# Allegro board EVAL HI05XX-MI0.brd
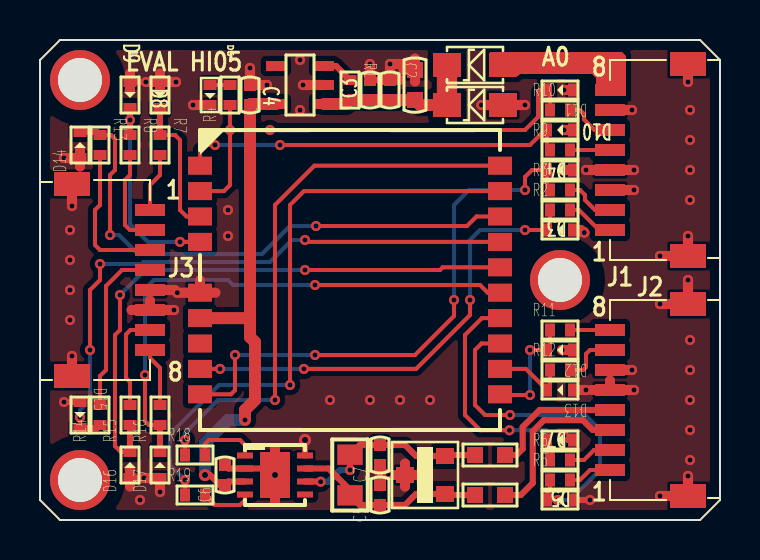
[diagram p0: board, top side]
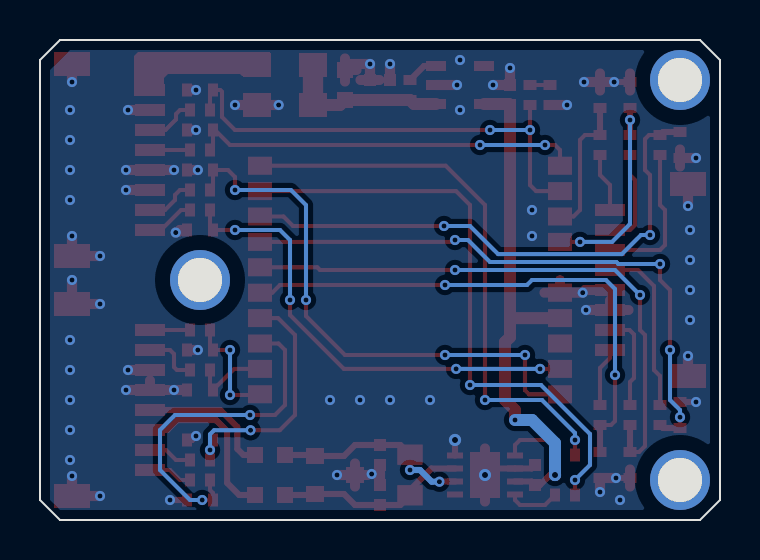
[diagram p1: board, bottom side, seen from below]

Outline 34 x 24 mm; copper layers: TOP, BOTTOM. Coordinates in mm from the lower left corner of the outline.
Outline path: 0,23 0,1 1,0 33,0 34,1 34,23 33,24 1,24 0,23

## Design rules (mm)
constraint set DEFAULT: min track width 0.203
net group CAN2: nets H L

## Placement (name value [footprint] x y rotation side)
C1  10uF  [C0603]  18.75 21.75 270 top
C2  0.1uF  [C0402]  17.5 21.5 270 top
C3  1uF  [C0402]  16.5 21.5 90 top
C4  1uF  [C0402]  10.5 21.25 270 top
C5  100pF  [C0402]  17 1.25 90 top
C6  0.1uF  [C0402]  9.25 2.25 90 top
C7  100pF  [C0402]  17 3.25 90 top
D1  1N5819  [SOD123FL]  21.75 22.75 0 top
D2  SDD32A05L01  [SOD123FL]  21.75 20.75 0 top
D3  SBD52C05L01  [SOD-523]  26 14.5 180 top
D4  SBD52C05L01  [SOD-523]  26 17.5 180 top
D5  SBD52C05L01  [SOD-523]  26 1 180 top
D6  GREEN  [LED0402]  8.5 21.25 270 top
D7  SBD52C05L01  [SOD-523]  26 4 180 top
D8  SBD52C05L01  [SOD-523]  6 21.25 270 top
D9  SBD52C05L01  [SOD-523]  4.5 21.25 270 top
D10  SBD52C05L01  [SOD-523]  26 19.5 180 top
D11  SBD52C05L01  [SOD-523]  26 21.5 180 top
D12  SBD52C05L01  [SOD-523]  26 8.5 180 top
D13  SBD52C05L01  [SOD-523]  26 6.5 180 top
D14  SBD52C05L01  [SOD-523]  2 18.75 90 top
D15  SBD52C05L01  [SOD-523]  2 5.25 270 top
D16  SBD52C05L01  [SOD-523]  4.5 2.75 90 top
D17  SBD52C05L01  [SOD-523]  6 2.75 90 top
D18  SM24CANB-02HTG  [SOT23-3-0_95]  19.25 2.25 90 top
F1  100mA  [F0603]  22.5 1.25 180 top
F2  100mA  [F0603]  22.5 3.25 180 top
H1  HOLE  [HOLE-2-MM]  2 22 0 top
H2  HOLE  [HOLE-2-MM]  2 2 0 top
H3  HOLE  [HOLE-2-MM]  26 12 0 top
J1  CON10  [5015680807_1]  28.5 18 270 top
J2  CON10  [5015680807_1]  28.5 6 270 top
J3  CON10  [5015680807_1]  5.5 12 90 top
R1  1K  [R0402]  15.5 21.5 270 top
R2  100R  [R0402]  26 15.5 0 top
R3  100R  [R0402]  26 16.5 0 top
R4  680R  [R0402]  9.5 21.25 90 top
R5  100R  [R0402]  26 2 0 top
R6  100R  [R0402]  26 3 0 top
R7  100R  [R0402]  6 18.75 270 top
R8  100R  [R0402]  4.5 18.75 270 top
R9  100R  [R0402]  26 18.5 0 top
R10  100R  [R0402]  26 20.5 0 top
R11  100R  [R0402]  26 9.5 0 top
R12  100R  [R0402]  26 7.5 0 top
R13  33R  [R0402]  3 18.75 270 top
R14  33R  [R0402]  3 5.25 90 top
R15  33R  [R0402]  4.5 5.25 90 top
R16  33R  [R0402]  6 5.25 90 top
R17  120R/DNP  [R0805]  15.5 2.25 270 top
R18  1K  [R0402]  7.75 3.25 0 top
R19  1K  [R0402]  7.75 1.25 0 top
U1  SPX3819M5-L-3-3/TR  [SOT23-5-0_95]  13 21.75 90 top
U2  HI05-MI0  [HI05]  15.5 12 0 top
U3  SIT3051TK  [HVSON8]  11.75 2.25 0 top

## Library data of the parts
C1-C7 = Capacity_Nonpolarity
D1 = diode
D2-D5 D7-D17 = DIODE BI-DIR TRIG
D6 = LED
D18 = BAT54A/SOT
F1 F2 = Fuse
H1-H3 = HOLE
J1-J3 = CON10
R1-R19 = Res
U1 = XC6210
U2 = HI05-MI0
U3 = SIT3051TK

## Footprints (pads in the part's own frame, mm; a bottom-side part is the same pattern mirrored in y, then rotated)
5015680807_1
  rect 0.6x1.5 smd: 1(3.5,0) 2(2.5,0) 3(1.5,0) 4(0.5,0) 5(-0.5,0) 6(-1.5,0) 7(-2.5,0) 8(-3.5,0)
  rect 1.2x1.8 smd: 9(4.8,3.9) 10(-4.8,3.9)
C0402
  rect 0.6x0.6 smd: 1(-0.5,0) 2(0.5,0)
C0603
  rect 0.8x0.8 smd: 1(-0.75,0) 2(0.75,0)
F0603
  rect 0.8x0.8 smd: 1(-0.75,0) 2(0.75,0)
HI05
  rect 1.2x0.9 smd: 1(-7.5,5.715) 2(-7.5,4.445) 3(-7.5,3.175) 4(-7.5,1.905) 5(-7.5,-0.635) 6(-7.5,-1.905) 7(-7.5,-3.175) 8(-7.5,-4.445) 9(-7.5,-5.715) 10(7.5,-5.715) 11(7.5,-4.445) 12(7.5,-3.175) 13(7.5,-1.905) 14(7.5,-0.635) 15(7.5,0.635) 16(7.5,1.905) 17(7.5,3.175) 18(7.5,4.445) 19(7.5,5.715)
HOLE-2-MM
  round 3 hole 2.2: 1(0,0)
HVSON8
  rect 0.8x0.3 smd: 1(-1.5,0.975) 2(-1.5,0.325) 3(-1.5,-0.325) 4(-1.5,-0.975) 5(1.5,-0.975) 6(1.5,-0.325) 7(1.5,0.325) 8(1.5,0.975)
  rect 1.5x2.3 smd: 9(0,0)
LED0402
  rect 0.5x0.65 smd: 1(-0.5,0) 2(0.5,0)
R0402
  rect 0.5x0.65 smd: 1(-0.5,0) 2(0.5,0)
R0805
  rect 1.016x1.27 smd: 1(-1.016,0) 2(1.016,0)
SOD123FL
  rect 1.4x1.2 smd: 1(1.4,0) 2(-1.4,0)
SOD-523
  rect 0.5x0.65 smd: 1(-0.65,0) 2(0.65,0)
SOT23-3-0_95
  rect 0.8x0.9 smd: 1(-0.95,-1) 2(0.95,-1) 3(0,1)
SOT23-5-0_95
  rect 0.5x1 smd: 1(-0.95,-1.2) 2(0,-1.2) 3(0.95,-1.2) 4(0.95,1.2) 5(-0.95,1.2)

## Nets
5V: D1.1(P) J1.8
GND: C1.1 C2.1 C3.2 C4.1 C5.2 C6.2 C7.1 D2.1 D3.1 D4.1 D5.1 D6.2(-) D7.1 D8.1 D9.1 D10.1 D11.1 D12.1 D13.1 D14.1 D15.1 D16.1 D17.1 D18.3 J1.3 J1.4 J1.7 J1.9 J1.10 J2.5 J2.6 J2.9 J2.10 J3.5 J3.6 J3.9 J3.10 U1.2(VSS) U2.5 U3.2 U3.8 U3.9
VCC: C1.2 C2.2 C3.1 D1.2 D2.2 R1.2 U1.1
CAN_RX: R19.1 U2.18
CAN_TX: R18.1 U2.19
CS: D17.2 R16.1 U2.14
DP3V3: C4.2 C6.1 U1.5 U2.6(VDD) U3.3(VCC)
H: F1.1 J2.3
L: F2.1 J2.4
MISO: D15.2 R14.1 U2.16
MOSI: D14.2 R13.1 U2.17
RST: U2.7
RXD1: D4.2 R3.1 U2.9
RXD2: D7.2 R6.1 U2.13
RXD3/SDA2: D13.2 R12.1 U2.11
RXD4: D9.2 R8.1 U2.4
SCK: D16.2 R15.1 U2.15
SIN/PPS: J1.5 R9.2
SOUT: J1.6 R10.2
SPI_CS: J3.8 R16.2
SPI_MISO: J3.4 R14.2
SPI_MOSI: J3.3 R13.2
SPI_SCK: J3.7 R15.2
SYNC_IN/PPS: D10.2 R9.1 U2.1
SYNC_OUT: D11.2 R4.1 R10.1 U2.2
TXD1: D3.2 R2.1 U2.8
TXD2: D5.2 R5.1 U2.12
TXD3/SCL2: D12.2 R11.1 U2.10
TXD4: D8.2 R7.1 U2.3
USART1_RX: J1.2 R3.2
USART1_TX: J1.1 R2.2
USART2_RX: J2.2 R6.2
USART2_TX: J2.1 R5.2
USART3_RX: J2.7 R12.2
USART3_TX: J2.8 R11.2
USART4_RX: J3.2 R8.2
USART4_TX: J3.1 R7.2
N2198535: D6.1 R4.2
N2215668: C5.1 D18.1 F1.2 R17.2 U3.7
N2215720: R18.2 U3.1
N2215758: C7.2 D18.2 F2.2 R17.1 U3.6
N2215796: R19.2 U3.4
N2224750: R1.1 U1.3

Pads without a net: H1 1; H2 1; H3 1; U1 4; U3 5

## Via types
v1: diameter 0.61, hole 0.305, TOP to BOTTOM, 3 vias
v2: diameter 0.508, hole 0.254, TOP to BOTTOM, 100 vias

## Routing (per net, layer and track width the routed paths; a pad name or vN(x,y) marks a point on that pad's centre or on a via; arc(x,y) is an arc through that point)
GND: length 61
  TOP w0.305: D7.1 26.4,4 v2(26.2,4.2) ; D5.1 v2(27.5,1) ; D9.1 v2(5.29,21.9) ; U3.8 v1(13.25,4) ; D16.1 v2(5.2,2.1) ; v1(11.75,2.25) 11.43,2.57 U3.2 9.43,2.57 C6.2 ; D15.1 v2(1.2,5.9)
  TOP w0.5: 18.17,22.5 C1.1 ; C1.1 18.75,21.92 ; C1.1 18.75,23.08 ; 17.02,22 C2.1 17.98,22 ; 4.5,1.67 D16.1 4.5,2.53 ; D8.1 6,22.33 ; D8.1 6,21.47 ; D8.1 5.5,21.9 ; 11.75,3.58 v1(11.75,2.25) 11.75,0.92 ; 28.5,6.98 J2.5 27.57,6.5 ; 8,11.99 U2.5 8.78,11.37 ; 2,17.67 D14.1 2,18.53 ; D18.3 18.25,2.83 ; D18.3 17.62,2.25 ; D18.3 18.25,1.67 ; 4.5,22.33 D9.1 4.5,21.47 ; 4.57,10.5 J3.6 5.5,10.98
  TOP w0.508: U1.2 v2(13.15,21.75) ; 17,2.3 v2(17.42,2.3) ; 17,2.3 C5.2 ; 17,2.3 C7.1 ; D8.1 v2(6.8,21.9) ; D13.1 v2(27.3,6.5) ; J3.5 6.73,11.5 v2(6.87,11.37) U2.5 ; J3.6 v2(6.7,10.5) ; C1.1 18.45,22.8 v2(17.5,22.8) C2.1 ; v2(27.3,17.5) J1.4 v2(29.7,17.5) ; D14.1 v2(1.2,18.1) ; v2(32.4,14.2) J1.9 v2(31,13.2) ; v2(24.25,20.75) D2.1 v2(22.07,20.75) ; J2.5 v2(29.7,6.5) ; D18.3 v2(19.15,2.25) ; D10.1 v2(26.2,19.5) ; D11.1 v2(26.2,21.5) ; v2(6,1.4) D17.1 v2(5.2,2.1) ; v2(10.5,22.6) C4.1 v2(11.35,21.75) ; J3.9 v2(1.6,15.7) ; D12.1 v2(26.11,8.5) ; D6.2 v2(7.65,20.75) ; D4.1 v2(26.11,17.5) ; v2(27.21,14.37) 27.18,14.4 27.1,14.4 27,14.5 D3.1 ; C3.2 v2(16.5,22.8) ; J2.6 v2(29.6,7.5) ; v2(31,1.2) J2.9 v2(32.4,2.2) ; v2(32.4,12) J2.10 v2(31,10.8) ; J1.7 v2(29.6,20.5) ; J1.3 v2(29.7,16.5) ; J3.10 v2(1.6,8.2) ; J1.10 v2(32.4,21.9)
  vias: v2(1.5,14.5) v2(1.5,13) v2(1.5,11.5) v2(1.5,10) v2(5,1) v2(9.4,15.5) v2(9.4,14.2) v2(13,23) v2(13,20.5) v2(14.5,6) v2(16.5,6) v2(18,6) v2(19.5,6) v2(32.5,20.5) v2(32.5,19) v2(32.5,17.5) v2(32.5,16) v2(32.5,9) v2(32.5,7.5) v2(32.5,6) v2(32.5,4.5) v2(32.5,3)
VCC: length 8.3
  TOP w0.6: D2.2 19,20.75 C1.2 C2.2 C3.1 R1.2 15.3,20.8 U1.1
  TOP w1.016: D1.2 D2.2
CAN_RX: length 30.2
  TOP w0.203: U2.18 13.2,16.45 12.5,15.75 v2(12.5,6.75) ; v2(7.25,2) R19.1
  BOTTOM w0.203: v2(7.25,2) 6.5,2.75 6.5,4.3 8.95,6.75 v2(12.5,6.75)
CAN_TX: length 28.1
  TOP w0.203: v2(7.25,4) R18.1 ; U2.19 13.71,17.71 11.75,15.75 v2(11.75,6)
  BOTTOM w0.203: v2(7.25,4) 7.25,4.35 8.9,6 v2(11.75,6)
CS: length 27
  TOP w0.203: R16.1 5.45,4.75 5.25,4.95 v2(5.25,7.25) ; v2(13.75,11.75) 22,11.75 22.38,11.37 U2.14
  TOP w0.305: R16.1 D17.2
  BOTTOM w0.203: v2(13.75,11.75) 9.65,11.75 9.4,12 5.7,12 5.25,11.55 v2(5.25,7.25)
DP3V3: length 26.3
  TOP w0.305: U3.3 9.43,1.93 C6.1 9,1.75 8.5,2.25 v1(8.25,2.25)
  TOP w0.6: U2.6 10.41,10.1 10.5,10 ; 10.5,10 10.5,9.14 10.75,8.89 10.75,6 10.25,5.5 v2(10.25,5) ; 10.5,10 C4.2 10.55,20.8 U1.5
  BOTTOM w0.6: v2(10.25,5) 9.4,5 8.25,3.85 v1(8.25,2.25)
H: length 8.5
  TOP w0.305: F1.1 24.04,1.25 24.64,1.85 24.64,4.44 25.19,4.99 27.14,4.99 27.63,4.5 J2.3
L: length 6.8
  TOP w0.305: F2.1 23.83,3.25 24.13,3.55 24.13,4.65 24.98,5.5 J2.4
MISO: length 30.3
  TOP w0.203: v2(2.5,8.5) 2.5,11.5 3,12 v2(3,12.8) ; v2(13.25,14) 13.35,13.9 U2.16 ; 2.06,5.08 v2(2,5.14) D15.2
  TOP w0.305: R14.1 2.85,4.6 D15.2
  BOTTOM w0.203: v2(2,5.14) 2,5.5 2.5,6 v2(2.5,8.5) ; v2(13.25,14) 12.6,14 11.5,12.9 5.18,12.9 5.08,12.8 v2(3,12.8)
MOSI: length 27.5
  TOP w0.203: v2(13.8,14.7) 21.35,14.7 21.82,15.18 U2.17 ; R13.1 3.55,19.25 3.75,19.05 3.75,17.5 3.5,17.25 v2(3.5,14.25)
  TOP w0.305: D14.2 2.85,19.4 R13.1
  BOTTOM w0.203: v2(13.8,14.7) 12.5,14.7 11.1,13.3 4.9,13.3 3.95,14.25 v2(3.5,14.25)
RXD1: length 27.7
  TOP w0.203: R3.1 25.35,16.65 D4.2 24.6,17.5 24.25,17.15 v2(24.25,16.5) ; U2.9 9.55,6.29 9.75,6.49 v2(9.75,8.25) ; v2(20.7,11) 20.7,10.2 18.75,8.25 v2(13.75,8.25)
  BOTTOM w0.203: v2(9.75,8.25) v2(13.75,8.25) ; v2(24.25,16.5) 21.45,16.5 20.7,15.75 v2(20.7,11)
RXD2: length 13.2
  TOP w0.203: v2(25.5,3.5) 25.35,3.65 D7.2 25.5,3.85 v2(25.5,3.5) ; v2(25.5,3.5) R6.1 ; U2.13 22.09,10.1 21.25,9.25 21.25,5.25 22.01,4.49 v2(23.47,4.49)
  BOTTOM w0.203: v2(23.47,4.49) 25.3,4.49 25.5,4.28 v2(25.5,3.5)
RXD3/SDA2: length 3.9
  TOP w0.203: 25.45,7.55 R12.1 25.5,6.65 D13.2 24.3,7.55 U2.11
RXD4: length 10.4
  TOP w0.203: U2.4 v2(7,13.9)
  TOP w0.305: D9.2 v2(4.5,20) R8.1
  BOTTOM w0.203: v2(4.5,20) 4.5,14.8 5.39,13.9 v2(7,13.9)
SCK: length 29.5
  TOP w0.203: U2.15 20.13,12.63 20,12.5 v2(13.25,12.5) ; v2(4,11.25) 4,9.5 3.75,9.25 3.75,3.7 4.05,3.4 D16.2
  TOP w0.305: R15.1 D16.2
  BOTTOM w0.203: v2(4,11.25) 5.25,12.5 v2(13.25,12.5)
SIN/PPS: length 2
  TOP w0.203: J1.5 R9.2
SOUT: length 2.6
  TOP w0.203: R10.2 27,20.5 27.2,20.3 27.2,20.03 27.73,19.5 J1.6
SPI_CS: length 3
  TOP w0.203: R16.2 6,7.6 5.5,8.1 J3.8
SPI_MISO: length 8.6
  TOP w0.203: J3.4 4.1,12.5 3.3,11.7 3.3,7.5 3,7.2 R14.2
SPI_MOSI: length 7.5
  TOP w0.203: R13.2 3,15.75 2.75,15.5 2.75,13.75 3,13.5 J3.3
SPI_SCK: length 4.9
  TOP w0.203: J3.7 4.52,9.5 4.3,9.28 4.3,7.1 4.5,6.9 R15.2
SYNC_IN/PPS: length 19.6
  TOP w0.203: v2(8.75,18.75) 8.25,18.75 8,18.5 U2.1 ; v2(12,18.75) 24.5,18.75 25.25,19.5 D10.2 25.35,18.65 R9.1
  BOTTOM w0.203: v2(12,18.75) v2(8.75,18.75)
SYNC_OUT: length 24.1
  TOP w0.203: R4.1 v2(9.5,19.5) 9.5,16.75 9.2,16.45 U2.2 ; R10.1 25.5,21.35 D11.2 24.98,21.5 24.9,21.42 24.9,20.15 24.25,19.5 v2(11.5,19.5)
  BOTTOM w0.203: v2(11.5,19.5) v2(9.5,19.5)
TXD1: length 23.5
  TOP w0.203: R2.1 25.5,14.65 D3.2 v2(24.25,14.5) ; U2.8 v2(9,7.55) ; v2(21.5,11) 21.5,10.25 18.8,7.55 v2(13.2,7.55)
  BOTTOM w0.203: v2(24.25,14.5) 22,14.5 21.5,14 v2(21.5,11) ; v2(9,7.55) v2(13.2,7.55)
TXD2: length 17.2
  TOP w0.203: R5.1 25.5,1.5 25.35,1.35 D5.2 v2(25.89,1) ; U2.12 22.07,8.82 21.75,8.5 21.75,5.75 22.25,5.25 v2(23.5,5.25)
  BOTTOM w0.203: v2(25.89,1) 26.5,1 28,2.5 28,4.5 27.25,5.25 v2(23.5,5.25)
TXD3/SCL2: length 5.7
  TOP w0.203: v2(24.5,6.25) 23.04,6.25 U2.10 ; R11.1 25.5,8.65 D12.2 v2(24.5,8.5)
  BOTTOM w0.203: v2(24.5,8.5) v2(24.5,6.25)
TXD4: length 7.1
  TOP w0.203: R7.1 6.75,19.25 7,19 7,15.5 7.32,15.18 U2.3
  TOP w0.305: D8.2 R7.1
USART1_RX: length 2.6
  TOP w0.203: R3.2 27,16.5 27.25,16.25 27.25,16 27.75,15.5 J1.2
USART1_TX: length 2.4
  TOP w0.203: R2.2 26.95,15.5 27.95,14.5 J1.1
USART2_RX: length 2.2
  TOP w0.203: R6.2 27.2,3 27.7,3.5 J2.2
USART2_TX: length 2.2
  TOP w0.203: J2.1 27.5,2.5 27,2 R5.2
USART3_RX: length 2.8
  TOP w0.203: J2.7 27.5,8.5 27.3,8.3 27.3,7.64 27.16,7.5 R12.2
USART3_TX: length 2
  TOP w0.203: J2.8 R11.2
USART4_RX: length 5
  TOP w0.203: R8.2 4.5,17.25 4.25,17 4.25,14.75 4.5,14.5 J3.2
USART4_TX: length 3
  TOP w0.203: R7.2 6,17.25 5.5,16.75 J3.1
N2198535: length 1
  TOP w0.203: D6.1 R4.2
N2215668: length 9.7
  TOP w0.305: F1.2 20.3,1.25 D18.1 18.8,1.3 18.25,0.75 C5.1 15.98,0.75 R17.2 15.5,1.5 14.43,2.57 U3.7
N2215720: length 3.3
  TOP w0.203: R18.2 8.25,3.8 8.45,4 10,4 10.25,3.75 U3.1
N2215758: length 10
  TOP w0.305: v2(15.5,2.5) R17.1 15.98,3.75 C7.2 18.25,3.75 18.8,3.2 D18.2 20.3,3.25 F2.2 ; U3.6 14.02,1.93 v2(14.03,1.91)
  BOTTOM w0.305: v2(14.03,1.91) 14.41,1.91 15,2.5 v2(15.5,2.5)
N2215796: length 2.6
  TOP w0.203: U3.4 10.25,1 10,0.75 8.75,0.75 R19.2
N2224750: length 1.6
  TOP w0.305: R1.1 14.8,22.7 U1.3

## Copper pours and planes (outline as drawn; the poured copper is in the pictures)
5V on TOP (solid shape): 29.3,23.2 29.3,21.2 27.8,21.2 27.8,22.1 27.6,22.3 24,22.3 23.9,22.2 22.5,22.2 22.5,23.4 29.1,23.4
GND on TOP: 1.5,23.5 32.5,23.5 33.5,22.5 33.5,1 33,0.5 1.5,0.5 0.5,1.5 0.5,22.5 ; 18 cut-outs
GND on BOTTOM: 1.5,23.5 32.5,23.5 33.5,22.5 33.5,1 33,0.5 1.5,0.5 0.5,1.5 0.5,22.5 ; 1 cut-out

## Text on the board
Ref Des/Silkscreen Top: EVAL HI05 | 1 | J3 | 8 | A0 | J1 | J2
User.8: FIGURE | FINISHED_SIZE | 10.0 | 12.0 | 20.0 | 86.614 | DRILL CHART: TOP to BOTTOM | ALL UNITS ARE IN MILS | PLATED | QTY | 126 | 2 | 3
